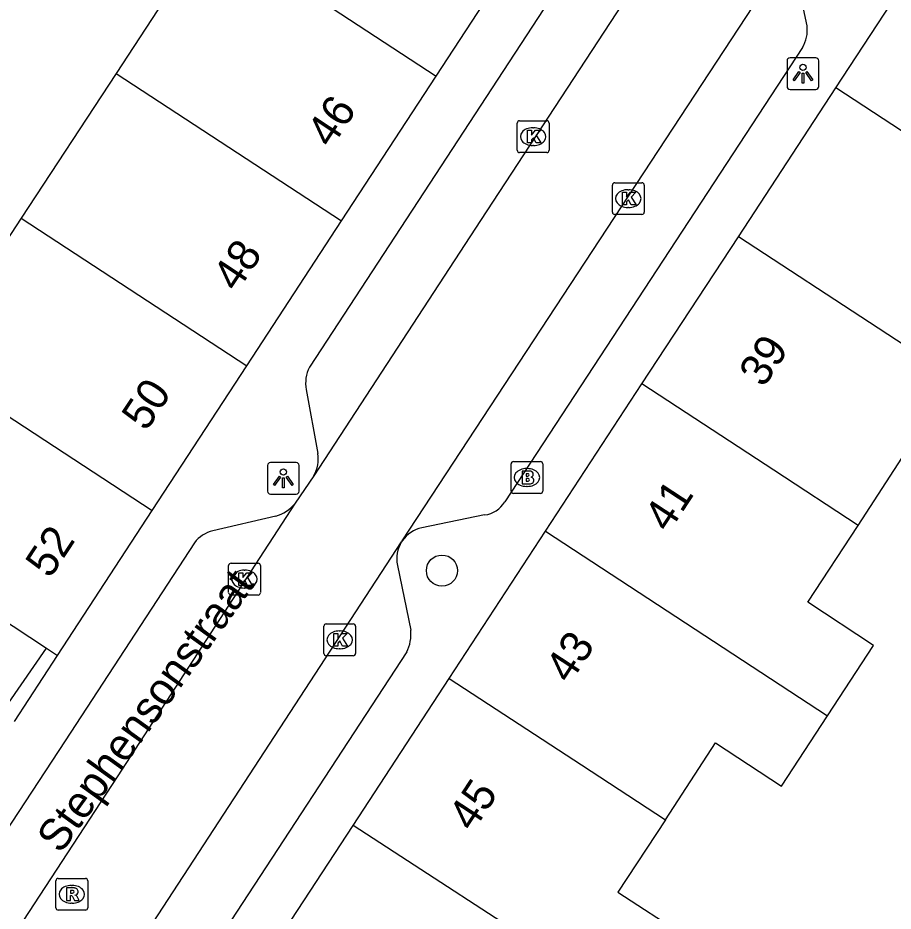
# Model space of a CAD drawing. Extents: x 159280 to 160375, y 384531 to 385872.
# Drawn here: x 159763.48 to 159791.01, y 384951.15 to 384979.23 of the extents above; entities that cross this region are included whole.
import ezdxf

# ---------------------------------------------------------------- set-up
doc = ezdxf.new("R2010")
doc.units = 0
for name, color, linetype in [('IMGEO_Boom', 7, 'Continuous'), ('IMGEO_Brandkraan', 7, 'Continuous'), ('IMGEO_Kolk', 7, 'Continuous'), ('IMGEO_Lichtpunt', 7, 'Continuous'), ('IMGEO_Openbare_ruimte_label', 7, 'Continuous'), ('IMGEO_Pand', 7, 'Continuous'), ('IMGEO_Pand_nummerreeks', 7, 'Continuous'), ('IMGEO_Rijbaan_lokaal_open', 7, 'Continuous'), ('IMGEO_Rioolput', 7, 'Continuous'), ('IMGEO_Voetpad_open', 7, 'Continuous')]:
    doc.layers.add(name, color=color, linetype=linetype)

msp = doc.modelspace()

# ---------------------------------------------------------------- linework, layer by layer
at = {"layer": 'IMGEO_Boom'}
msp.add_circle((159776.822, 384961.852), 0.489, dxfattribs=at)
at = {"layer": 'IMGEO_Brandkraan'}
for p, q in [((159778.993, 384964.355), (159778.993, 384965.207)), ((159779.068, 384965.281), (159779.92, 384965.281)), ((159779.481, 384965.061), (159779.506, 384965.061)), ((159779.994, 384965.207), (159779.994, 384964.355)), ((159779.504, 384964.501), (159779.479, 384964.501)), ((159779.92, 384964.281), (159779.068, 384964.281))]:
    msp.add_line(p, q, dxfattribs=at)
for points in [[(159778.993, 384964.355), (159778.993, 384965.207)], [(159779.068, 384965.281), (159779.92, 384965.281)], [(159779.994, 384965.207), (159779.994, 384964.355)], [(159779.341, 384964.981), (159779.341, 384964.581), (159779.554, 384964.581)], [(159779.572, 384964.981), (159779.341, 384964.981)], [(159779.52, 384964.9), (159779.466, 384964.9), (159779.466, 384964.824)], [(159779.466, 384964.824), (159779.519, 384964.824)], [(159779.528, 384964.748), (159779.466, 384964.748), (159779.466, 384964.667)], [(159779.466, 384964.667), (159779.528, 384964.667)], [(159779.92, 384964.281), (159779.068, 384964.281)]]:
    msp.add_lwpolyline(points, dxfattribs=at)
for centre, radius, start, end in [((159779.07, 384965.205), 0.0765, 91.552, 178.448), ((159779.07, 384965.205), 0.0765, 91.552, 178.448), ((159779.918, 384965.205), 0.0765, 1.552, 88.448), ((159779.918, 384965.205), 0.0765, 1.552, 88.448), ((159779.521, 384964.862), 0.0379, 267.8285, 90.9355), ((159779.576, 384964.836), 0.145, 59.4692, 91.5367), ((159779.601, 384964.883), 0.0922, 285.5137, 58.1501), ((159779.606, 384964.691), 0.105, 301.3115, 78.989), ((159779.529, 384964.707), 0.0404, 269.8759, 90.5077), ((159779.56, 384964.832), 0.251, 268.6676, 293.5347), ((159779.07, 384964.357), 0.0765, 181.552, 268.448), ((159779.07, 384964.357), 0.0765, 181.552, 268.448), ((159779.918, 384964.357), 0.0765, 271.552, 358.448), ((159779.918, 384964.357), 0.0765, 271.552, 358.448)]:
    msp.add_arc(centre, radius, start, end, dxfattribs=at)
for centre, major_axis, ratio, start_param, end_param in [((159779.48, 384964.781), (-0.387, 0.002), 0.722429, 4.712389, 7.853982), ((159779.505, 384964.781), (-0.39, 0.002), 0.717154, 1.570796, 4.712389)]:
    msp.add_ellipse(centre, major_axis=major_axis, ratio=ratio, start_param=start_param, end_param=end_param, dxfattribs=at)
at = {"layer": 'IMGEO_Kolk'}
for p, q in [((159779.188, 384975.071), (159779.188, 384975.923)), ((159779.263, 384975.997), (159780.115, 384975.997)), ((159779.676, 384975.777), (159779.701, 384975.777)), ((159780.189, 384975.923), (159780.189, 384975.071)), ((159779.699, 384975.217), (159779.674, 384975.217)), ((159780.115, 384974.997), (159779.263, 384974.997)), ((159782.255, 384974.049), (159783.107, 384974.049)), ((159782.18, 384973.123), (159782.18, 384973.975)), ((159782.668, 384973.829), (159782.693, 384973.829)), ((159783.181, 384973.975), (159783.181, 384973.123)), ((159782.691, 384973.269), (159782.666, 384973.269)), ((159783.107, 384973.049), (159782.255, 384973.049)), ((159770.112, 384961.16), (159770.112, 384962.012)), ((159770.187, 384962.086), (159771.039, 384962.086)), ((159771.113, 384962.012), (159771.113, 384961.16)), ((159770.6, 384961.866), (159770.625, 384961.866)), ((159770.623, 384961.306), (159770.598, 384961.306)), ((159771.039, 384961.086), (159770.187, 384961.086)), ((159773.105, 384959.251), (159773.105, 384960.103)), ((159773.18, 384960.177), (159774.032, 384960.177)), ((159774.106, 384960.103), (159774.106, 384959.251)), ((159773.593, 384959.957), (159773.618, 384959.957)), ((159774.032, 384959.177), (159773.18, 384959.177)), ((159773.616, 384959.397), (159773.591, 384959.397))]:
    msp.add_line(p, q, dxfattribs=at)
for points in [[(159779.188, 384975.071), (159779.188, 384975.923)], [(159779.263, 384975.997), (159780.115, 384975.997)], [(159780.189, 384975.923), (159780.189, 384975.071)], [(159779.509, 384975.697), (159779.632, 384975.697), (159779.632, 384975.546), (159779.762, 384975.697), (159779.926, 384975.697), (159779.78, 384975.546), (159779.933, 384975.297), (159779.781, 384975.297), (159779.696, 384975.461), (159779.632, 384975.394), (159779.632, 384975.297), (159779.509, 384975.297), (159779.509, 384975.697)], [(159780.115, 384974.997), (159779.263, 384974.997)], [(159782.255, 384974.049), (159783.107, 384974.049)], [(159782.18, 384973.123), (159782.18, 384973.975)], [(159783.181, 384973.975), (159783.181, 384973.123)], [(159782.501, 384973.749), (159782.624, 384973.749), (159782.624, 384973.598), (159782.754, 384973.749), (159782.918, 384973.749), (159782.772, 384973.598), (159782.925, 384973.349), (159782.773, 384973.349), (159782.688, 384973.513), (159782.624, 384973.446), (159782.624, 384973.349), (159782.501, 384973.349), (159782.501, 384973.749)], [(159783.107, 384973.049), (159782.255, 384973.049)], [(159770.112, 384961.16), (159770.112, 384962.012)], [(159770.187, 384962.086), (159771.039, 384962.086)], [(159771.113, 384962.012), (159771.113, 384961.16)], [(159770.433, 384961.786), (159770.556, 384961.786), (159770.556, 384961.635), (159770.686, 384961.786), (159770.85, 384961.786), (159770.704, 384961.635), (159770.857, 384961.386), (159770.705, 384961.386), (159770.62, 384961.55), (159770.556, 384961.483), (159770.556, 384961.386), (159770.433, 384961.386), (159770.433, 384961.786)], [(159771.039, 384961.086), (159770.187, 384961.086)], [(159773.105, 384959.251), (159773.105, 384960.103)], [(159773.18, 384960.177), (159774.032, 384960.177)], [(159774.106, 384960.103), (159774.106, 384959.251)], [(159773.426, 384959.877), (159773.549, 384959.877), (159773.549, 384959.726), (159773.679, 384959.877), (159773.843, 384959.877), (159773.697, 384959.726), (159773.85, 384959.477), (159773.698, 384959.477), (159773.613, 384959.641), (159773.549, 384959.574), (159773.549, 384959.477), (159773.426, 384959.477), (159773.426, 384959.877)], [(159774.032, 384959.177), (159773.18, 384959.177)]]:
    msp.add_lwpolyline(points, dxfattribs=at)
for centre, start, end in [((159779.265, 384975.921), 91.552, 178.448), ((159779.265, 384975.921), 91.552, 178.448), ((159780.113, 384975.921), 1.552, 88.448), ((159780.113, 384975.921), 1.552, 88.448), ((159779.265, 384975.073), 181.552, 268.448), ((159779.265, 384975.073), 181.552, 268.448), ((159780.113, 384975.073), 271.552, 358.448), ((159780.113, 384975.073), 271.552, 358.448), ((159782.257, 384973.973), 91.552, 178.448), ((159782.257, 384973.973), 91.552, 178.448), ((159783.105, 384973.973), 1.552, 88.448), ((159783.105, 384973.973), 1.552, 88.448), ((159782.257, 384973.125), 181.552, 268.448), ((159782.257, 384973.125), 181.552, 268.448), ((159783.105, 384973.125), 271.552, 358.448), ((159783.105, 384973.125), 271.552, 358.448), ((159770.189, 384962.01), 91.552, 178.448), ((159770.189, 384962.01), 91.552, 178.448), ((159771.037, 384962.01), 1.552, 88.448), ((159771.037, 384962.01), 1.552, 88.448), ((159770.189, 384961.162), 181.552, 268.448), ((159770.189, 384961.162), 181.552, 268.448), ((159771.037, 384961.162), 271.552, 358.448), ((159771.037, 384961.162), 271.552, 358.448), ((159773.182, 384960.101), 91.552, 178.448), ((159773.182, 384960.101), 91.552, 178.448), ((159774.03, 384960.101), 1.552, 88.448), ((159774.03, 384960.101), 1.552, 88.448), ((159773.182, 384959.253), 181.552, 268.448), ((159773.182, 384959.253), 181.552, 268.448), ((159774.03, 384959.253), 271.552, 358.448), ((159774.03, 384959.253), 271.552, 358.448)]:
    msp.add_arc(centre, 0.0765, start, end, dxfattribs=at)
for centre, major_axis, ratio, start_param, end_param in [((159779.675, 384975.497), (-0.387, 0.002), 0.722429, 4.712389, 7.853982), ((159779.7, 384975.497), (-0.39, 0.002), 0.717154, 1.570796, 4.712389), ((159782.667, 384973.549), (-0.387, 0.002), 0.722429, 4.712389, 7.853982), ((159782.692, 384973.549), (-0.39, 0.002), 0.717154, 1.570796, 4.712389), ((159770.599, 384961.586), (-0.387, 0.002), 0.722429, 4.712389, 7.853982), ((159770.624, 384961.586), (-0.39, 0.002), 0.717154, 1.570796, 4.712389), ((159773.592, 384959.677), (-0.387, 0.002), 0.722429, 4.712389, 7.853982), ((159773.617, 384959.677), (-0.39, 0.002), 0.717154, 1.570796, 4.712389)]:
    msp.add_ellipse(centre, major_axis=major_axis, ratio=ratio, start_param=start_param, end_param=end_param, dxfattribs=at)
at = {"layer": 'IMGEO_Lichtpunt'}
for p, q in [((159788.577, 384977.975), (159787.769, 384977.975)), ((159788.577, 384977.975), (159787.769, 384977.975)), ((159787.675, 384977.88), (159787.675, 384977.073)), ((159787.675, 384977.88), (159787.675, 384977.073)), ((159788.671, 384977.073), (159788.671, 384977.88)), ((159788.671, 384977.073), (159788.671, 384977.88)), ((159787.769, 384976.979), (159788.577, 384976.979)), ((159787.769, 384976.979), (159788.577, 384976.979)), ((159771.335, 384965.158), (159771.335, 384964.351)), ((159771.335, 384965.158), (159771.335, 384964.351)), ((159772.237, 384965.253), (159771.429, 384965.253)), ((159772.237, 384965.253), (159771.429, 384965.253)), ((159772.331, 384964.351), (159772.331, 384965.158)), ((159772.331, 384964.351), (159772.331, 384965.158)), ((159771.429, 384964.257), (159772.237, 384964.257)), ((159771.429, 384964.257), (159772.237, 384964.257))]:
    msp.add_line(p, q, dxfattribs=at)
for points in [[(159788.049, 384977.544), (159788.088, 384977.516), (159787.9, 384977.254), (159787.862, 384977.281), (159788.049, 384977.544)], [(159788.151, 384977.496), (159788.198, 384977.496), (159788.198, 384977.174), (159788.151, 384977.174), (159788.151, 384977.496)], [(159788.261, 384977.516), (159788.299, 384977.543), (159788.486, 384977.281), (159788.447, 384977.253), (159788.261, 384977.516)], [(159771.709, 384964.822), (159771.748, 384964.794), (159771.56, 384964.532), (159771.522, 384964.559), (159771.709, 384964.822)], [(159771.811, 384964.774), (159771.858, 384964.774), (159771.858, 384964.452), (159771.811, 384964.452), (159771.811, 384964.774)], [(159771.921, 384964.794), (159771.959, 384964.821), (159772.146, 384964.559), (159772.107, 384964.531), (159771.921, 384964.794)]]:
    msp.add_lwpolyline(points, dxfattribs=at)
for centre in [(159788.174, 384977.678), (159771.834, 384964.956)]:
    msp.add_circle(centre, 0.0994, dxfattribs=at)
for centre, start, end in [((159787.769, 384977.88), 90, 180), ((159787.769, 384977.88), 90, 180), ((159788.577, 384977.88), 0, 90), ((159788.577, 384977.88), 0, 90), ((159787.769, 384977.073), 180, 270), ((159787.769, 384977.073), 180, 270), ((159788.577, 384977.073), 270, 0), ((159788.577, 384977.073), 270, 360), ((159771.429, 384965.158), 90, 180), ((159771.429, 384965.158), 90, 180), ((159772.237, 384965.158), 0, 90), ((159772.237, 384965.158), 0, 90), ((159771.429, 384964.351), 180, 270), ((159771.429, 384964.351), 180, 270), ((159772.237, 384964.351), 270, 0), ((159772.237, 384964.351), 270, 360)]:
    msp.add_arc(centre, 0.0946, start, end, dxfattribs=at)
at = {"layer": 'IMGEO_Pand'}
for points in [[(159769.554, 384982.036), (159766.571, 384977.485)], [(159769.554, 384982.036), (159776.64, 384977.402)], [(159776.64, 384977.402), (159779.618, 384981.956)], [(159789.206, 384977.032), (159792.266, 384981.707)], [(159766.571, 384977.485), (159763.589, 384972.935)], [(159766.571, 384977.485), (159773.663, 384972.849)], [(159773.663, 384972.849), (159776.64, 384977.402)], [(159786.142, 384972.35), (159789.206, 384977.032)], [(159795.999, 384972.585), (159793.333, 384974.33), (159789.206, 384977.032)], [(159763.589, 384972.935), (159760.88, 384968.803)], [(159763.589, 384972.935), (159770.685, 384968.295)], [(159770.685, 384968.295), (159773.663, 384972.849)], [(159783.112, 384967.722), (159786.142, 384972.35)], [(159794.91, 384966.611), (159790.539, 384969.471), (159786.142, 384972.35)], [(159760.606, 384968.384), (159767.707, 384963.741)], [(159767.707, 384963.741), (159770.685, 384968.295)], [(159780.082, 384963.093), (159783.112, 384967.722)], [(159789.906, 384963.276), (159787.255, 384965.011), (159783.112, 384967.722)], [(159789.906, 384963.276), (159791.423, 384965.594), (159793.398, 384964.301), (159794.91, 384966.611)], [(159764.729, 384959.187), (159767.707, 384963.741)], [(159758.087, 384963.565), (159764.387, 384959.412)], [(159777.053, 384958.465), (159780.082, 384963.093)], [(159780.082, 384963.093), (159784.48, 384960.215), (159788.95, 384957.289)], [(159788.95, 384957.289), (159790.397, 384959.5), (159788.323, 384960.858), (159789.906, 384963.276)], [(159764.387, 384959.412), (159764.729, 384959.187)], [(159774.024, 384953.837), (159777.053, 384958.465)], [(159777.053, 384958.465), (159781.211, 384955.744), (159783.847, 384954.019)], [(159783.847, 384954.019), (159785.428, 384956.435), (159787.502, 384955.077), (159788.95, 384957.289)], [(159770.929, 384949.108), (159774.024, 384953.837)], [(159780.832, 384949.413), (159774.024, 384953.837)], [(159783.847, 384954.019), (159782.357, 384951.743), (159784.413, 384950.398)]]:
    msp.add_lwpolyline(points, dxfattribs=at)
at = {"layer": 'IMGEO_Rijbaan_lokaal_open'}
for points in [[(159785.415, 384984.141), (159778.035, 384972.859), (159772.788, 384964.838)], [(159775.573, 384962.788), (159788.002, 384981.726)], [(159772.788, 384964.838), (159772.21, 384963.971)], [(159772.21, 384963.971), (159766.607, 384955.365), (159751.984, 384933.016), (159750.513, 384930.769)], [(159766.465, 384948.834), (159775.553, 384962.757)], [(159775.573, 384962.788), (159775.553, 384962.757)]]:
    msp.add_lwpolyline(points, dxfattribs=at)
at = {"layer": 'IMGEO_Rioolput'}
for p, q in [((159764.755, 384952.178), (159765.607, 384952.178)), ((159764.68, 384951.252), (159764.68, 384952.104)), ((159765.168, 384951.958), (159765.193, 384951.958)), ((159765.681, 384952.104), (159765.681, 384951.252)), ((159765.191, 384951.398), (159765.166, 384951.398)), ((159765.607, 384951.178), (159764.755, 384951.178))]:
    msp.add_line(p, q, dxfattribs=at)
for points in [[(159764.755, 384952.178), (159765.607, 384952.178)], [(159764.68, 384951.252), (159764.68, 384952.104)], [(159765.269, 384951.876), (159765.017, 384951.878), (159765.017, 384951.478)], [(159765.681, 384952.104), (159765.681, 384951.252)], [(159765.017, 384951.478), (159765.141, 384951.478), (159765.141, 384951.64), (159765.152, 384951.64)], [(159765.195, 384951.797), (159765.141, 384951.797), (159765.141, 384951.716)], [(159765.141, 384951.716), (159765.193, 384951.716)], [(159765.199, 384951.611), (159765.27, 384951.478), (159765.41, 384951.478), (159765.345, 384951.604)], [(159765.607, 384951.178), (159764.755, 384951.178)]]:
    msp.add_lwpolyline(points, dxfattribs=at)
for centre, radius, start, end in [((159764.757, 384952.102), 0.0765, 91.552, 178.448), ((159764.757, 384952.102), 0.0765, 91.552, 178.448), ((159765.605, 384952.102), 0.0765, 1.552, 88.448), ((159765.605, 384952.102), 0.0765, 1.552, 88.448), ((159765.268, 384951.766), 0.109, 350.3612, 89.416), ((159765.151, 384951.587), 0.0533, 26.0293, 88.6989), ((159765.177, 384951.905), 0.19, 274.7715, 282.9687), ((159765.201, 384951.701), 0.0964, 77.0061, 93.1865), ((159765.215, 384951.758), 0.0378, 276.6634, 79.6772), ((159765.266, 384951.766), 0.112, 277.5842, 350.9817), ((159765.25, 384951.551), 0.108, 29.5134, 73.7905), ((159764.757, 384951.254), 0.0765, 181.552, 268.448), ((159764.757, 384951.254), 0.0765, 181.552, 268.448), ((159765.605, 384951.254), 0.0765, 271.552, 358.448), ((159765.605, 384951.254), 0.0765, 271.552, 358.448)]:
    msp.add_arc(centre, radius, start, end, dxfattribs=at)
for centre, major_axis, ratio, start_param, end_param in [((159765.167, 384951.678), (-0.387, 0.002), 0.722429, 4.712389, 7.853982), ((159765.192, 384951.678), (-0.39, 0.002), 0.717154, 1.570796, 4.712389)]:
    msp.add_ellipse(centre, major_axis=major_axis, ratio=ratio, start_param=start_param, end_param=end_param, dxfattribs=at)
at = {"layer": 'IMGEO_Voetpad_open'}
for points in [[(159782.342, 384983.067), (159772.652, 384968.251)], [(159787.864, 384980.986), (159788.301, 384978.978)], [(159788.155, 384978.297), (159778.796, 384964.013)], [(159772.553, 384967.543), (159772.92, 384965.533)], [(159771.592, 384963.564), (159769.617, 384963.1)], [(159778.162, 384963.606), (159776.19, 384963.202)], [(159769.04, 384962.73), (159764.971, 384956.505), (159750.29, 384934.127)], [(159775.42, 384962.019), (159775.841, 384959.978)], [(159756.912, 384961.797), (159763.189, 384957.685), (159764.387, 384959.412)], [(159763.379, 384957.108), (159764.729, 384959.187)], [(159775.716, 384959.296), (159769.626, 384949.995)]]:
    msp.add_lwpolyline(points, dxfattribs=at)
for centre, radius, start, end in [((159787.28, 384978.841), 1.031, 328.1509, 7.6481), ((159773.67, 384967.748), 1.136, 153.6919, 190.3879), ((159771.859, 384965.375), 1.073, 330.0031, 8.4889), ((159771.191, 384964.846), 1.344, 287.3832, 319.3527), ((159778.067, 384964.451), 0.851, 276.4101, 328.9872), ((159769.807, 384962.169), 0.95, 101.5315, 143.8083), ((159776.397, 384962.227), 0.997, 101.9875, 145.7348), ((159776.403, 384962.223), 1.004, 147.8457, 191.7222), ((159774.562, 384959.86), 1.284, 333.9548, 5.2729)]:
    msp.add_arc(centre, radius, start, end, dxfattribs=at)

# ---------------------------------------------------------------- texts
at = {"layer": 'IMGEO_Openbare_ruimte_label'}
msp.add_text('Stephensonstraat', height=1, rotation=54.1959, dxfattribs=at).set_placement((159764.825, 384952.919))
at = {"layer": 'IMGEO_Pand_nummerreeks'}
for s, rotation, p in [('46', 56.6197, (159773.341, 384975.103)), ('48', 56.6197, (159770.38, 384970.575)), ('39', 56.7941, (159786.938, 384967.577)), ('50', 56.6197, (159767.521, 384966.202)), ('41', 56.7941, (159783.952, 384963.014)), ('52', 56.6197, (159764.495, 384961.575)), ('43', 56.7941, (159780.842, 384958.263)), ('45', 56.7916, (159777.794, 384953.606))]:
    msp.add_text(s, height=1, rotation=rotation, dxfattribs=at).set_placement(p)

doc.saveas('drawing.dxf')
